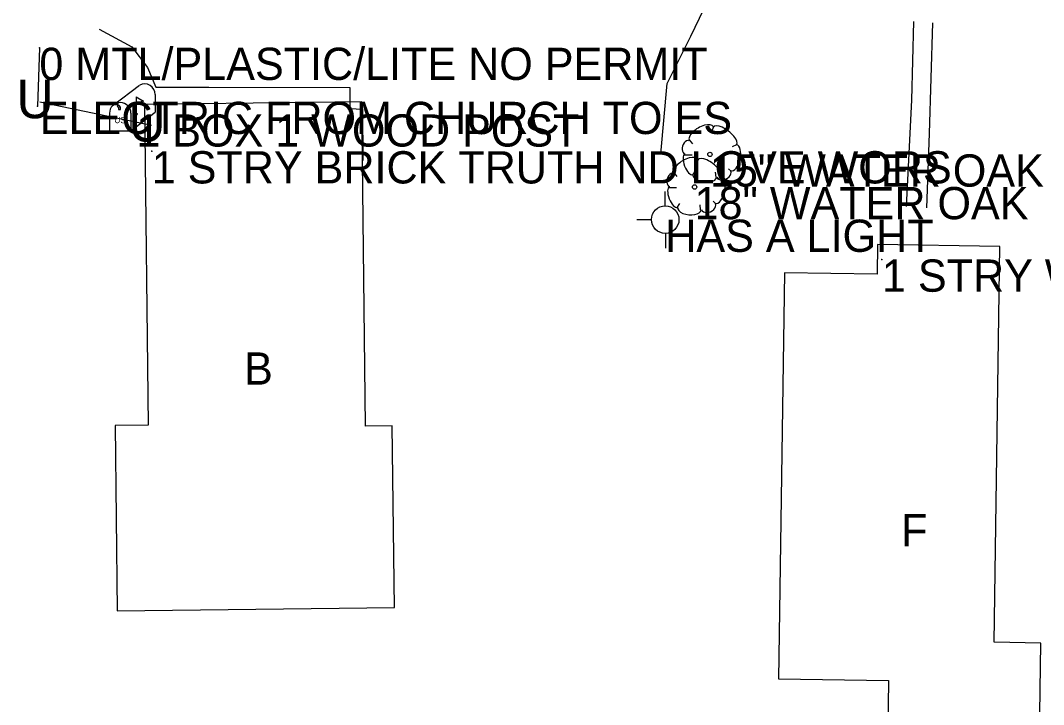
# Model space of a CAD drawing. Extents: x 1304270 to 1306561, y 1876019 to 1876752.
# Drawn here: x 1305433.8 to 1305592.5, y 1876274.2 to 1876380.2 of the extents above; entities that cross this region are included whole.
import ezdxf

# ---------------------------------------------------------------- set-up
doc = ezdxf.new("R2010")
doc.units = 0
for name, color, linetype in [('S_BUILDING', 7, 'Continuous'), ('S_BUILDING_ANNOT', 7, 'Continuous'), ('S_MAILBOX', 7, 'Continuous'), ('S_MAILBOX_ANNOT', 7, 'Continuous'), ('S_MSC_PT_SYM', 7, 'Continuous'), ('S_PARKING', 7, 'Continuous'), ('S_SIDEWALK', 7, 'Continuous'), ('S_SIGN', 7, 'Continuous'), ('S_SIGN_ANNOT', 7, 'Continuous'), ('S_STR_PT_SYM', 7, 'Continuous'), ('S_TREE', 7, 'Continuous'), ('S_TREE_ANNOT', 7, 'Continuous'), ('S_UNDERGROUND_CABLE', 7, 'Continuous'), ('S_UNDERGROUND_CABLE_ANNOT', 7, 'Continuous'), ('S_UTILITY_POLE', 7, 'Continuous'), ('S_UTILITY_POLE_ANNOT', 7, 'Continuous'), ('S_UTL_PT_SYM', 7, 'Continuous')]:
    doc.layers.add(name, color=color, linetype=linetype)

msp = doc.modelspace()

# ---------------------------------------------------------------- linework, layer by layer
at = {"layer": 'S_BUILDING'}
for points in [[(1305487.37, 1876317.32), (1305486.77, 1876367.63), (1305453.06, 1876367.22), (1305453.66, 1876317.49), (1305448.51, 1876317.43), (1305448.86, 1876288.69), (1305491.83, 1876289.2), (1305491.49, 1876317.37)], [(1305552.34, 1876341.12), (1305551.44, 1876278.14), (1305568.5, 1876277.9), (1305568.22, 1876258.47), (1305591.76, 1876258.14), (1305592.12, 1876283.7), (1305584.84, 1876283.81), (1305585.72, 1876345.21), (1305566.76, 1876345.48), (1305566.7, 1876340.91)]]:
    msp.add_lwpolyline(points, close=True, dxfattribs=at)
at = {"layer": 'S_MAILBOX'}
for p, q in [((1305448.2, 1876367.12), (1305452.33, 1876370.23)), ((1305451.81, 1876368.41), (1305451.81, 1876365.69)), ((1305454.76, 1876368.75), (1305454.76, 1876366.04)), ((1305447.64, 1876365.85), (1305447.64, 1876363.13)), ((1305450.97, 1876363.13), (1305454.76, 1876366.04)), ((1305450.97, 1876365.85), (1305450.97, 1876363.13)), ((1305447.64, 1876363.13), (1305450.97, 1876363.13))]:
    msp.add_line(p, q, dxfattribs=at)
for points in [[(1305451.81, 1876368.41), (1305452.92, 1876367.74), (1305451.81, 1876367.4)], [(1305448.83, 1876366.96), (1305449.05, 1876366.82), (1305449.05, 1876366.43), (1305449.35, 1876366.43), (1305449.35, 1876366.79), (1305449.16, 1876367.04), (1305448.83, 1876366.99)]]:
    msp.add_lwpolyline(points, dxfattribs=at)
for centre, end in [((1305453.1, 1876368.75), 117.5718), ((1305449.31, 1876365.85), 180)]:
    msp.add_arc(centre, 1.66, 0, end, dxfattribs=at)
msp.add_ellipse((1305451.81, 1876365.69), major_axis=(0.145, 0.132), ratio=0.564646, dxfattribs=at)
at = {"layer": 'S_MSC_PT_SYM'}
for points in [[(1305436.77, 1876376.02), (1305436.77, 1876376.07), (1305436.77, 1876376.02), (1305436.72, 1876376.02), (1305436.77, 1876376.02), (1305436.77, 1876375.97), (1305436.77, 1876376.02), (1305436.82, 1876376.02)], [(1305436.5, 1876366.94), (1305436.5, 1876366.99), (1305436.5, 1876366.94), (1305436.45, 1876366.94), (1305436.5, 1876366.94), (1305436.5, 1876366.89), (1305436.5, 1876366.94), (1305436.55, 1876366.94)]]:
    msp.add_lwpolyline(points, dxfattribs=at)
at = {"layer": 'S_PARKING'}
for points in [[(1305533.16, 1876359.56), (1305534.16, 1876370.45), (1305537.81, 1876377.8), (1305540.53, 1876383.43)], [(1305446.05, 1876378.88), (1305451.11, 1876376.16), (1305453.52, 1876372.97), (1305454.84, 1876369.91), (1305463.04, 1876369.88), (1305484.92, 1876369.83), (1305484.95, 1876366.58), (1305486.9, 1876366.49), (1305486.94, 1876358.52)]]:
    msp.add_lwpolyline(points, dxfattribs=at)
at = {"layer": 'S_SIDEWALK'}
for points in [[(1305572.37, 1876380.07), (1305572.06, 1876367.91), (1305571.24, 1876351.42)], [(1305574.43, 1876351.21), (1305574.82, 1876362.7), (1305575.34, 1876379.87)]]:
    msp.add_lwpolyline(points, dxfattribs=at)
at = {"layer": 'S_SIGN'}
msp.add_line((1305436.77, 1876376.02), (1305436.5, 1876366.94), dxfattribs=at)
at = {"layer": 'S_STR_PT_SYM'}
for points in [[(1305454.2, 1876359.97), (1305454.2, 1876360.02), (1305454.2, 1876359.97), (1305454.15, 1876359.97), (1305454.2, 1876359.97), (1305454.2, 1876359.92), (1305454.2, 1876359.97), (1305454.25, 1876359.97)], [(1305567.46, 1876343.18), (1305567.46, 1876343.23), (1305567.46, 1876343.18), (1305567.41, 1876343.18), (1305567.46, 1876343.18), (1305567.46, 1876343.13), (1305567.46, 1876343.18), (1305567.51, 1876343.18)]]:
    msp.add_lwpolyline(points, dxfattribs=at)
at = {"layer": 'S_TREE'}
for p, q in [((1305541.34, 1876363.73), (1305540.95, 1876362.88)), ((1305537.54, 1876361.71), (1305538.05, 1876361.13)), ((1305544.9, 1876360.94), (1305544.25, 1876360.67)), ((1305536.88, 1876359.39), (1305538.01, 1876359.39)), ((1305538.96, 1876358.67), (1305538.57, 1876357.82)), ((1305544.13, 1876356.83), (1305543.66, 1876357.26)), ((1305535.16, 1876356.65), (1305535.66, 1876356.07)), ((1305538.05, 1876356.21), (1305538.51, 1876356.91)), ((1305541.73, 1876355.94), (1305541.65, 1876356.71)), ((1305542.52, 1876355.88), (1305541.86, 1876355.61)), ((1305534.5, 1876354.33), (1305535.62, 1876354.33)), ((1305535.66, 1876351.15), (1305536.13, 1876351.85)), ((1305539.34, 1876350.88), (1305539.27, 1876351.65)), ((1305541.75, 1876351.77), (1305541.28, 1876352.2))]:
    msp.add_line(p, q, dxfattribs=at)
for centre in [(1305540.78, 1876359.48), (1305538.4, 1876354.42)]:
    msp.add_circle(centre, 0.341, dxfattribs=at)
for centre, major_axis, ratio, start_param, end_param in [((1305539.45, 1876362.69), (1.86, 1.08), 0.471018, 0, 3.141593), ((1305543.1, 1876362.36), (-1.81, 1.36), 0.405113, 3.141593, 6.283186), ((1305537.21, 1876360.57), (0.31, 1.03), 0.646762, 0, 3.141593), ((1305544.46, 1876358.95), (0.46, 2.04), 0.482994, 3.141593, 6.283185), ((1305537.06, 1876357.62), (1.86, 1.08), 0.471018, 0, 3.141593), ((1305537.52, 1876357.92), (-0.61, 1.6), 0.420543, 6.283185, 9.424777), ((1305540.72, 1876357.3), (-1.81, 1.36), 0.405113, 3.141593, 6.283186), ((1305534.83, 1876355.51), (0.31, 1.03), 0.646762, 0, 3.141593), ((1305539.98, 1876356.14), (-1.83, 0.19), 0.529943, 0, 3.141593), ((1305542.07, 1876353.89), (0.46, 2.04), 0.482994, 3.141593, 6.283185), ((1305542.93, 1876356.43), (1.09, 0.46), 0.711534, 3.141592, 6.283185), ((1305535.13, 1876352.86), (-0.61, 1.6), 0.420543, 6.283185, 9.424777), ((1305537.59, 1876351.08), (-1.83, 0.19), 0.529943, 0, 3.141593), ((1305540.55, 1876351.37), (1.09, 0.46), 0.711534, 3.141592, 6.283185)]:
    msp.add_ellipse(centre, major_axis=major_axis, ratio=ratio, start_param=start_param, end_param=end_param, dxfattribs=at)
at = {"layer": 'S_UNDERGROUND_CABLE'}
msp.add_line((1305436.85, 1876367.63), (1305454.18, 1876364.01), dxfattribs=at)
at = {"layer": 'S_UTILITY_POLE'}
for p, q in [((1305533.84, 1876351.47), (1305533.84, 1876353.71)), ((1305531.75, 1876349.33), (1305529.43, 1876349.33)), ((1305533.92, 1876344.92), (1305533.92, 1876347.24))]:
    msp.add_line(p, q, dxfattribs=at)
msp.add_circle((1305533.85, 1876349.36), 2.13, dxfattribs=at)

# ---------------------------------------------------------------- texts
at = {"layer": 'S_BUILDING_ANNOT'}
for s, p in [('1 STRY BRICK TRUTH ND LOVE WORS', (1305454.2, 1876354.97)), ('1 STRY WOOD', (1305567.46, 1876338.18)), ('B', (1305468.53, 1876323.77)), ('F', (1305570.44, 1876298.7))]:
    msp.add_text(s, height=5, dxfattribs=at).set_placement(p)
at = {"layer": 'S_MAILBOX'}
msp.add_text('US', height=0.96, rotation=360, dxfattribs=at).set_placement((1305448.41, 1876364.32))
at = {"layer": 'S_MAILBOX_ANNOT'}
msp.add_text('1 BOX 1 WOOD POST', height=5, dxfattribs=at).set_placement((1305451.81, 1876360.69))
at = {"layer": 'S_SIGN_ANNOT'}
msp.add_text('0 MTL/PLASTIC/LITE NO PERMIT', height=5, dxfattribs=at).set_placement((1305436.77, 1876371.02))
at = {"layer": 'S_TREE_ANNOT'}
for s, p in [('15" WATER OAK', (1305540.78, 1876354.48)), ('18" WATER OAK', (1305538.4, 1876349.42))]:
    msp.add_text(s, height=5, dxfattribs=at).set_placement(p)
at = {"layer": 'S_UNDERGROUND_CABLE_ANNOT'}
msp.add_text('ELECTRIC FROM CHURCH TO ES', height=5, dxfattribs=at).set_placement((1305436.85, 1876362.63))
at = {"layer": 'S_UTILITY_POLE_ANNOT'}
msp.add_text('HAS A LIGHT', height=5, dxfattribs=at).set_placement((1305533.85, 1876344.36))
at = {"layer": 'S_UTL_PT_SYM'}
for p in [(1305433.22, 1876365.08), (1305450.55, 1876361.46)]:
    msp.add_text('U', height=6, rotation=360, dxfattribs=at).set_placement(p)

doc.saveas('drawing.dxf')
